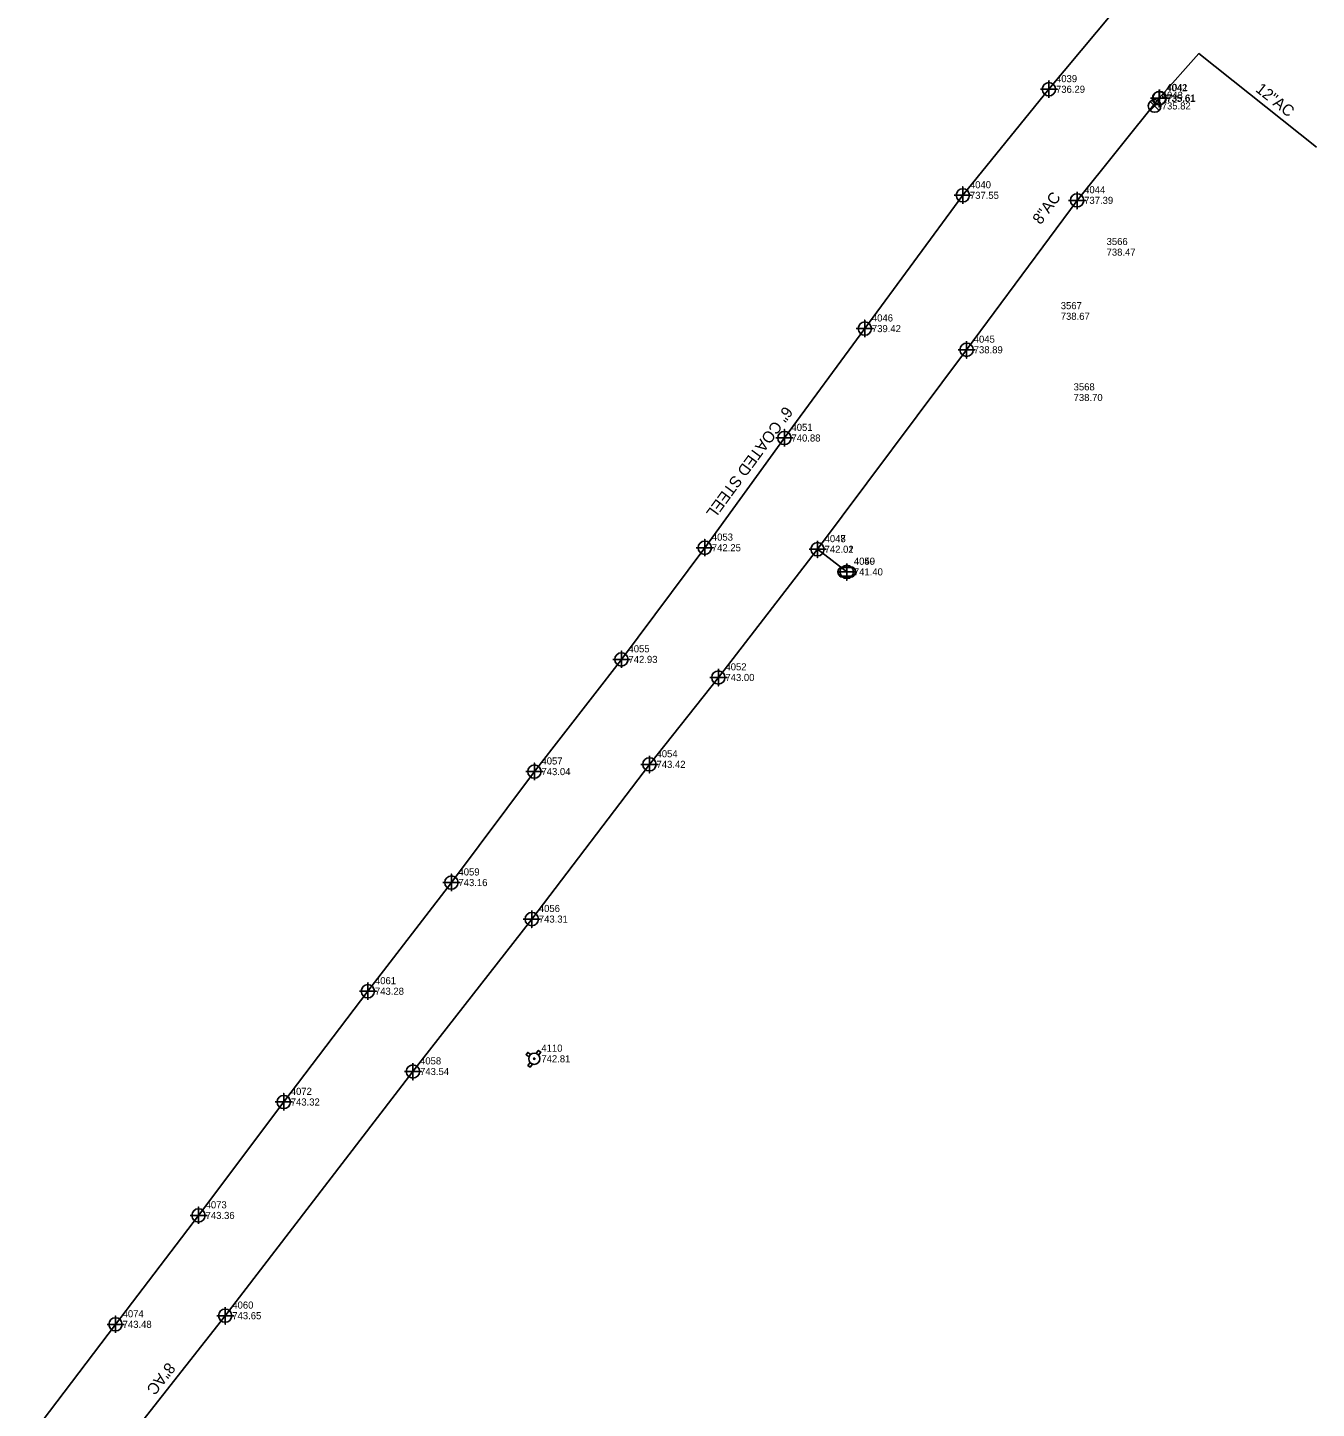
# Model space of a CAD drawing. Extents: x 1622486 to 1624761, y 758733 to 760816.
# Drawn here: x 1622949.4 to 1623403.7, y 759180.5 to 759667.2 of the extents above; entities that cross this region are included whole.
import ezdxf

# ---------------------------------------------------------------- set-up
doc = ezdxf.new("R2010")
doc.units = 0
for name, color, linetype in [('Exist Other Culture Area Outline Cogo Elevation', 7, 'Continuous'), ('Exist Other Culture Area Outline Cogo Number', 7, 'Continuous'), ('Exist Structure Minor Catch Basin Top Elevation', 7, 'Continuous'), ('Exist Structure Minor Pipes RCP 15 Inch Invert', 7, 'Continuous'), ('Exist Structure Minor Pipes RCP 30 Inch Text', 7, 'Continuous'), ('Exist Utilities Gas UG Line SUE', 7, 'Continuous'), ('Exist Utilities Gas UG Line SUE Cogo Elevation', 7, 'Continuous'), ('Exist Utilities Gas UG Line SUE Cogo Number', 7, 'Continuous'), ('Exist Utilities Gas UG Line SUE Cogo Point CELL', 7, 'Continuous'), ('Exist Utilities Water Fire Hydrant CELL', 7, 'Continuous'), ('Exist Utilities Water Fire Hydrant Cogo Elevation', 7, 'Continuous'), ('Exist Utilities Water Fire Hydrant Cogo Number', 7, 'Continuous'), ('Exist Utilities Water Meter CELL', 7, 'Continuous'), ('Exist Utilities Water Meter Cogo Elevation', 7, 'Continuous'), ('Exist Utilities Water Meter Cogo Number', 7, 'Continuous'), ('Exist Utilities Water UG Line', 7, 'Continuous'), ('Exist Utilities Water UG Line SUE', 7, 'Continuous'), ('Exist Utilities Water UG Line SUE Cogo Elevation', 7, 'Continuous'), ('Exist Utilities Water UG Line SUE Cogo Number', 7, 'Continuous'), ('Exist Utilities Water UG Line SUE Cogo Point CELL', 7, 'Continuous'), ('Exist Utilities Water Valve CELL', 7, 'Continuous'), ('Exist Utilities Water Valve Cogo Elevation', 7, 'Continuous'), ('Exist Utilities Water Valve Cogo Number', 7, 'Continuous')]:
    doc.layers.add(name, color=color, linetype=linetype)

msp = doc.modelspace()

# ---------------------------------------------------------------- linework, layer by layer
at = {"layer": 'Exist Utilities Gas UG Line SUE'}
msp.add_lwpolyline([(1623337.57, 759679.35), (1623309.44, 759645.45), (1623279.08, 759608.07), (1623244.53, 759561.1), (1623216.18, 759522.54), (1623188.11, 759483.86), (1623158.72, 759444.49), (1623128.04, 759404.95), (1623098.78, 759365.83), (1623069.34, 759327.52), (1623039.67, 759288.49), (1623009.64, 759248.5), (1622980.39, 759210.11), (1622949.39, 759169.17)], dxfattribs=at)
at = {"layer": 'Exist Utilities Gas UG Line SUE Cogo Point CELL'}
for points in [[(1623306.44, 759645.45), (1623312.44, 759645.45), (1623309.44, 759645.45), (1623309.44, 759648.45), (1623309.44, 759642.45)], [(1623276.08, 759608.07), (1623282.08, 759608.07), (1623279.08, 759608.07), (1623279.08, 759611.07), (1623279.08, 759605.07)], [(1623241.53, 759561.1), (1623247.53, 759561.1), (1623244.53, 759561.1), (1623244.53, 759564.1), (1623244.53, 759558.1)], [(1623213.18, 759522.54), (1623219.18, 759522.54), (1623216.18, 759522.54), (1623216.18, 759525.54), (1623216.18, 759519.54)], [(1623185.11, 759483.86), (1623191.11, 759483.86), (1623188.11, 759483.86), (1623188.11, 759486.86), (1623188.11, 759480.86)], [(1623155.72, 759444.49), (1623161.72, 759444.49), (1623158.72, 759444.49), (1623158.72, 759447.49), (1623158.72, 759441.49)], [(1623125.04, 759404.95), (1623131.04, 759404.95), (1623128.04, 759404.95), (1623128.04, 759407.95), (1623128.04, 759401.95)], [(1623095.78, 759365.83), (1623101.78, 759365.83), (1623098.78, 759365.83), (1623098.78, 759368.83), (1623098.78, 759362.83)], [(1623066.34, 759327.52), (1623072.34, 759327.52), (1623069.34, 759327.52), (1623069.34, 759330.52), (1623069.34, 759324.52)], [(1623036.67, 759288.49), (1623042.67, 759288.49), (1623039.67, 759288.49), (1623039.67, 759291.49), (1623039.67, 759285.49)], [(1623006.64, 759248.5), (1623012.64, 759248.5), (1623009.64, 759248.5), (1623009.64, 759251.5), (1623009.64, 759245.5)], [(1622977.39, 759210.11), (1622983.39, 759210.11), (1622980.39, 759210.11), (1622980.39, 759213.11), (1622980.39, 759207.11)]]:
    msp.add_lwpolyline(points, dxfattribs=at)
for centre in [(1623309.44, 759645.45), (1623279.08, 759608.07), (1623244.53, 759561.1), (1623216.18, 759522.54), (1623188.11, 759483.86), (1623158.72, 759444.49), (1623128.04, 759404.95), (1623098.78, 759365.83), (1623069.34, 759327.52), (1623039.67, 759288.49), (1623009.64, 759248.5), (1622980.39, 759210.11)]:
    msp.add_circle(centre, 2.34, dxfattribs=at)
at = {"layer": 'Exist Utilities Water Fire Hydrant CELL'}
msp.add_line((1623128.01, 759303.72), (1623128.01, 759303.72), dxfattribs=at)
for points in [[(1623126.74, 759305.24), (1623125.68, 759305.97), (1623125.09, 759305.13), (1623126.15, 759304.39)], [(1623128.68, 759305.59), (1623129.42, 759306.65), (1623130.26, 759306.06), (1623129.51, 759304.98)], [(1623126.5, 759302.45), (1623125.77, 759301.39), (1623126.61, 759300.8), (1623127.36, 759301.88)]]:
    msp.add_lwpolyline(points, dxfattribs=at)
for radius in [1.98, 0.243]:
    msp.add_circle((1623128.01, 759303.72), radius, dxfattribs=at)
at = {"layer": 'Exist Utilities Water Meter CELL'}
msp.add_line((1623238.18, 759475.35), (1623238.18, 759475.35), dxfattribs=at)
for points in [[(1623236.14, 759477.05), (1623240.22, 759477.05)], [(1623236.14, 759476.91), (1623240.22, 759476.91)], [(1623240.22, 759473.78), (1623236.12, 759473.78)], [(1623240.22, 759473.65), (1623236.12, 759473.65)]]:
    msp.add_lwpolyline(points, dxfattribs=at)
for centre, radius, start, end in [((1623236.87, 759475.34), 1.86, 113.178, 245.9794), ((1623236.88, 759475.34), 1.73, 115.3009, 243.7824), ((1623239.47, 759475.35), 1.86, 293.6483, 66.3084), ((1623239.48, 759475.35), 1.73, 295.1272, 64.8728)]:
    msp.add_arc(centre, radius, start, end, dxfattribs=at)
at = {"layer": 'Exist Utilities Water UG Line'}
msp.add_lwpolyline([(1623348.28, 759642.26), (1623362.32, 759658.02), (1623403.73, 759625.07)], dxfattribs=at)
at = {"layer": 'Exist Utilities Water UG Line SUE'}
msp.add_line((1623227.86, 759483.31), (1623238.17, 759475.34), dxfattribs=at)
msp.add_lwpolyline([(1622962.92, 759141.34), (1622983.04, 759167.36), (1623019.05, 759213.17), (1623085.24, 759299.23), (1623127.12, 759352.96), (1623168.6, 759407.5), (1623192.9, 759438.13), (1623227.86, 759483.32), (1623280.43, 759553.63), (1623319.36, 759606.3), (1623348.28, 759642.26)], dxfattribs=at)
at = {"layer": 'Exist Utilities Water UG Line SUE Cogo Point CELL'}
for points in [[(1623348.28, 759645.26), (1623348.28, 759639.26), (1623348.28, 759642.26), (1623351.28, 759642.26), (1623345.28, 759642.26)], [(1623348.47, 759645.37), (1623348.47, 759639.37), (1623348.47, 759642.37), (1623351.47, 759642.37), (1623345.47, 759642.37)], [(1623319.36, 759609.3), (1623319.36, 759603.3), (1623319.36, 759606.3), (1623322.36, 759606.3), (1623316.36, 759606.3)], [(1623280.43, 759556.63), (1623280.43, 759550.63), (1623280.43, 759553.63), (1623283.43, 759553.63), (1623277.43, 759553.63)], [(1623227.86, 759486.32), (1623227.86, 759480.32), (1623227.86, 759483.32), (1623230.86, 759483.32), (1623224.86, 759483.32)], [(1623227.86, 759486.31), (1623227.86, 759480.31), (1623227.86, 759483.31), (1623230.86, 759483.31), (1623224.86, 759483.31)], [(1623238.17, 759478.34), (1623238.17, 759472.34), (1623238.17, 759475.34), (1623241.17, 759475.34), (1623235.17, 759475.34)], [(1623192.9, 759441.13), (1623192.9, 759435.13), (1623192.9, 759438.13), (1623195.9, 759438.13), (1623189.9, 759438.13)], [(1623168.6, 759410.5), (1623168.6, 759404.5), (1623168.6, 759407.5), (1623171.6, 759407.5), (1623165.6, 759407.5)], [(1623127.12, 759355.96), (1623127.12, 759349.96), (1623127.12, 759352.96), (1623130.12, 759352.96), (1623124.12, 759352.96)], [(1623085.24, 759302.23), (1623085.24, 759296.23), (1623085.24, 759299.23), (1623088.24, 759299.23), (1623082.24, 759299.23)], [(1623019.05, 759216.17), (1623019.05, 759210.17), (1623019.05, 759213.17), (1623022.05, 759213.17), (1623016.05, 759213.17)]]:
    msp.add_lwpolyline(points, dxfattribs=at)
for centre in [(1623348.28, 759642.26), (1623348.47, 759642.37), (1623319.36, 759606.3), (1623280.43, 759553.63), (1623227.86, 759483.32), (1623227.86, 759483.31), (1623238.17, 759475.34), (1623192.9, 759438.13), (1623168.6, 759407.5), (1623127.12, 759352.96), (1623085.24, 759299.23), (1623019.05, 759213.17)]:
    msp.add_circle(centre, 2.34, dxfattribs=at)
at = {"layer": 'Exist Utilities Water Valve CELL'}
msp.add_lwpolyline([(1623348.28, 759641.16), (1623345.13, 759638.01), (1623346.71, 759639.59), (1623348.28, 759638.01), (1623345.13, 759641.16)], dxfattribs=at)
msp.add_circle((1623346.71, 759639.59), 2.23, dxfattribs=at)

# ---------------------------------------------------------------- texts
at = {"layer": 'Exist Other Culture Area Outline Cogo Elevation'}
for s, p in [('738.47', (1623329.77, 759586.8)), ('738.67', (1623313.61, 759564.19)), ('738.70', (1623318.15, 759535.56))]:
    msp.add_text(s, height=2.5, dxfattribs=at).set_placement(p)
at = {"layer": 'Exist Other Culture Area Outline Cogo Number'}
for s, p in [('3566', (1623329.77, 759590.55)), ('3567', (1623313.61, 759567.94)), ('3568', (1623318.15, 759539.31))]:
    msp.add_text(s, height=2.5, dxfattribs=at).set_placement(p)
at = {"layer": 'Exist Structure Minor Catch Basin Top Elevation'}
msp.add_text('8"AC', height=4, rotation=53.5325, dxfattribs=at).set_placement((1623306.52, 759597.49))
at = {"layer": 'Exist Structure Minor Pipes RCP 15 Inch Invert'}
for s, rotation, p in [('12"AC', 321.4949, (1623381.98, 759644.93)), ('8"AC', 231.6759, (1622998.71, 759196.99))]:
    msp.add_text(s, height=4, rotation=rotation, dxfattribs=at).set_placement(p)
at = {"layer": 'Exist Structure Minor Pipes RCP 30 Inch Text'}
msp.add_text('6" COATED STEEL', height=4, rotation=233.6834, dxfattribs=at).set_placement((1623216.26, 759534.01))
at = {"layer": 'Exist Utilities Gas UG Line SUE Cogo Elevation'}
for s, p in [('736.29', (1623311.94, 759644.2)), ('737.55', (1623281.58, 759606.82)), ('739.42', (1623247.03, 759559.85)), ('740.88', (1623218.68, 759521.29)), ('742.25', (1623190.61, 759482.61)), ('742.93', (1623161.22, 759443.24)), ('743.04', (1623130.54, 759403.7)), ('743.16', (1623101.28, 759364.58)), ('743.28', (1623071.84, 759326.27)), ('743.32', (1623042.17, 759287.24)), ('743.36', (1623012.14, 759247.25)), ('743.48', (1622982.89, 759208.86))]:
    msp.add_text(s, height=2.5, dxfattribs=at).set_placement(p)
at = {"layer": 'Exist Utilities Gas UG Line SUE Cogo Number'}
for s, p in [('4039', (1623311.94, 759647.95)), ('4040', (1623281.58, 759610.57)), ('4046', (1623247.03, 759563.6)), ('4051', (1623218.68, 759525.04)), ('4053', (1623190.61, 759486.36)), ('4055', (1623161.22, 759446.99)), ('4057', (1623130.54, 759407.45)), ('4059', (1623101.28, 759368.33)), ('4061', (1623071.84, 759330.02)), ('4072', (1623042.17, 759290.99)), ('4073', (1623012.14, 759251)), ('4074', (1622982.89, 759212.61))]:
    msp.add_text(s, height=2.5, dxfattribs=at).set_placement(p)
at = {"layer": 'Exist Utilities Water Fire Hydrant Cogo Elevation'}
msp.add_text('742.81', height=2.5, dxfattribs=at).set_placement((1623130.51, 759302.47))
at = {"layer": 'Exist Utilities Water Fire Hydrant Cogo Number'}
msp.add_text('4110', height=2.5, dxfattribs=at).set_placement((1623130.51, 759306.22))
at = {"layer": 'Exist Utilities Water Meter Cogo Elevation'}
msp.add_text('741.40', height=2.5, dxfattribs=at).set_placement((1623240.68, 759474.1))
at = {"layer": 'Exist Utilities Water Meter Cogo Number'}
msp.add_text('4050', height=2.5, dxfattribs=at).set_placement((1623240.68, 759477.85))
at = {"layer": 'Exist Utilities Water UG Line SUE Cogo Elevation'}
for s, p in [('735.61', (1623350.78, 759641.01)), ('735.61', (1623350.97, 759641.12)), ('737.39', (1623321.86, 759605.05)), ('738.89', (1623282.93, 759552.38)), ('742.02', (1623230.36, 759482.06)), ('742.01', (1623230.36, 759482.07)), ('741.40', (1623240.67, 759474.09)), ('743.00', (1623195.4, 759436.88)), ('743.42', (1623171.1, 759406.25)), ('743.31', (1623129.62, 759351.71)), ('743.54', (1623087.74, 759297.98)), ('743.65', (1623021.55, 759211.92))]:
    msp.add_text(s, height=2.5, dxfattribs=at).set_placement(p)
at = {"layer": 'Exist Utilities Water UG Line SUE Cogo Number'}
for s, p in [('4042', (1623350.78, 759644.76)), ('4041', (1623350.97, 759644.87)), ('4044', (1623321.86, 759608.8)), ('4045', (1623282.93, 759556.13)), ('4047', (1623230.36, 759485.82)), ('4048', (1623230.36, 759485.81)), ('4049', (1623240.67, 759477.84)), ('4052', (1623195.4, 759440.63)), ('4054', (1623171.1, 759410)), ('4056', (1623129.62, 759355.46)), ('4058', (1623087.74, 759301.73)), ('4060', (1623021.55, 759215.67))]:
    msp.add_text(s, height=2.5, dxfattribs=at).set_placement(p)
at = {"layer": 'Exist Utilities Water Valve Cogo Elevation'}
msp.add_text('735.82', height=2.5, dxfattribs=at).set_placement((1623349.21, 759638.34))
at = {"layer": 'Exist Utilities Water Valve Cogo Number'}
msp.add_text('4043', height=2.5, dxfattribs=at).set_placement((1623349.21, 759642.09))

doc.saveas('drawing.dxf')
